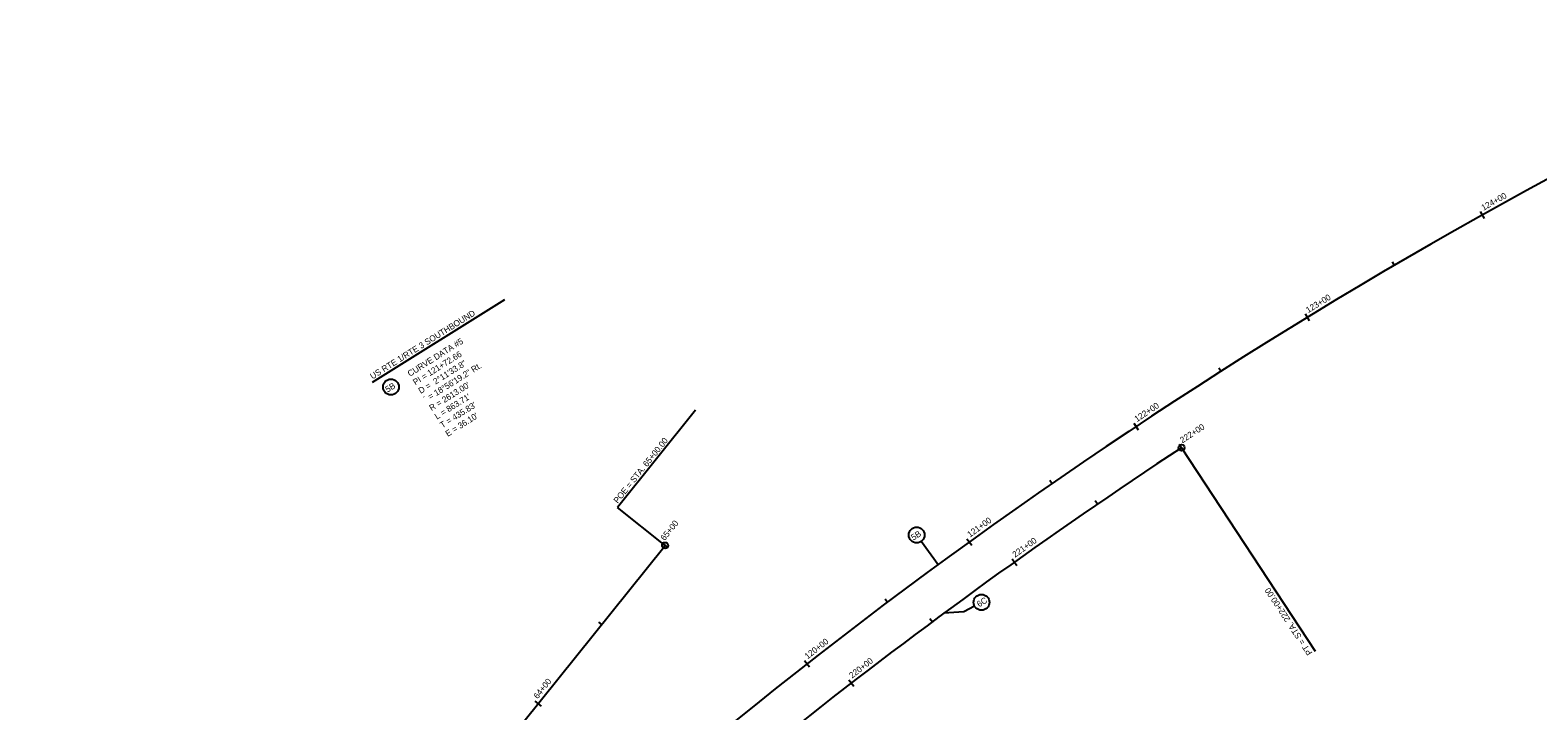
# Model space of a CAD drawing. Extents: x 1667099 to 1669772, y 337408 to 340124.
# Drawn here: x 1667828 to 1668571, y 339310 to 339645 of the extents above; entities that cross this region are included whole.
import ezdxf

# ---------------------------------------------------------------- set-up
doc = ezdxf.new("R2010")
doc.units = 0
for name, color, linetype in [('Alignment', 7, 'Continuous'), ('ANNOTATION', 7, 'Continuous'), ('D_Roadway_Centerline', 7, 'Continuous'), ('D_Roadway_Centerline_CurveData', 7, 'Continuous'), ('D_Roadway_Centerline_Flags', 7, 'Continuous'), ('D_Roadway_Centerline_Text', 7, 'Continuous'), ('Default', 7, 'Continuous'), ('S_Roadway_Edge_Pavement', 7, 'Continuous')]:
    doc.layers.add(name, color=color, linetype=linetype)

msp = doc.modelspace()

# ---------------------------------------------------------------- linework, layer by layer
at = {"layer": 'Alignment'}
msp.add_arc((1669829.28, 337256.22), 2612, 123.30352, 133.53618, dxfattribs=at)
at = {"layer": 'ANNOTATION'}
for p, q in [((1667996.45, 339471.53), (1668061.61, 339512.39)), ((1668266.88, 339393.07), (1668275.23, 339381.66)), ((1668293.09, 339361.15), (1668287.75, 339358.27)), ((1668287.75, 339358.27), (1668277.9, 339357.59))]:
    msp.add_line(p, q, dxfattribs=at)
for centre in [(1668005.47, 339469.19), (1668264.57, 339396.21), (1668296.52, 339363)]:
    msp.add_circle(centre, 3.9, dxfattribs=at)
at = {"layer": 'D_Roadway_Centerline'}
msp.add_line((1667827.67, 339001.09), (1668140.6, 339391.06), dxfattribs=at)
for centre, radius, start, end in [((1669819.48, 337273.8), 2613, 114.83733, 133.776), ((1669829.28, 337256.22), 2612, 123.30352, 133.53618)]:
    msp.add_arc(centre, radius, start, end, dxfattribs=at)
at = {"layer": 'D_Roadway_Centerline_Flags'}
msp.add_line((1668155.64, 339457.73), (1668117.2, 339409.84), dxfattribs=at)
for points in [[(1668395.1, 339439.26), (1668460.99, 339338.97)], [(1668140.6, 339391.06), (1668117.2, 339409.84)]]:
    msp.add_lwpolyline(points, dxfattribs=at)
for centre in [(1668395.1, 339439.26), (1668140.6, 339391.06)]:
    msp.add_circle(centre, 1.5, dxfattribs=at)
at = {"layer": 'D_Roadway_Centerline_Text'}
for points in [[(1668542.35, 339555.72), (1668544.3, 339552.23)], [(1668498.92, 339530.87), (1668499.93, 339529.14)], [(1668455.97, 339505.19), (1668458.06, 339501.77)], [(1668413.53, 339478.69), (1668414.6, 339477)], [(1668371.6, 339451.39), (1668373.81, 339448.05)], [(1668394, 339440.93), (1668396.2, 339437.59)], [(1668394, 339440.93), (1668396.2, 339437.59)], [(1668330.2, 339423.28), (1668331.34, 339421.64)], [(1668352.59, 339413.15), (1668353.71, 339411.5)], [(1668139.04, 339392.31), (1668142.16, 339389.81)], [(1668289.34, 339394.39), (1668291.68, 339391.15)], [(1668311.57, 339384.49), (1668313.89, 339381.24)], [(1668249.05, 339364.73), (1668250.25, 339363.13)], [(1668107.75, 339353.31), (1668109.31, 339352.06)], [(1668271.11, 339355.05), (1668272.3, 339353.45)], [(1668209.33, 339334.3), (1668211.79, 339331.14)], [(1668231.22, 339324.84), (1668233.67, 339321.68)], [(1668076.45, 339314.32), (1668079.57, 339311.81)]]:
    msp.add_lwpolyline(points, dxfattribs=at)
at = {"layer": 'Default'}
msp.add_line((1667827.67, 339001.09), (1668140.6, 339391.06), dxfattribs=at)
at = {"layer": 'S_Roadway_Edge_Pavement'}
msp.add_arc((1669819.48, 337273.8), 2613, 114.83733, 133.776, dxfattribs=at)

# ---------------------------------------------------------------- texts
at = {"layer": 'ANNOTATION'}
for s, rotation, p in [('US RTE 1/RTE 3 SOUTHBOUND', 32.08927, (1667996.38, 339472.84)), ('5B', 31.85504, (1668003.86, 339466.4)), ('5B', 31.85504, (1668262.96, 339393.42)), ('6C', 32.55289, (1668295.43, 339360.5))]:
    msp.add_text(s, height=3, rotation=rotation, dxfattribs=at).set_placement(p)
at = {"layer": 'D_Roadway_Centerline_CurveData'}
for s, p in [('CURVE DATA #5', (1668014.85, 339474.18)), ('PI = 121+72.66', (1668017.51, 339469.95)), ('D =  2%%d11\'33.8"', (1668020.18, 339465.72)), ('´ = 18%%d56\'19.2" Rt.', (1668022.84, 339461.49)), ("R = 2613.00'", (1668025.5, 339457.26)), ("L = 863.71'", (1668028.17, 339453.03)), ("T = 435.83'", (1668030.83, 339448.79)), ("E = 36.10'", (1668033.49, 339444.56))]:
    msp.add_text(s, height=3, rotation=32.18617, dxfattribs=at).set_placement(p)
at = {"layer": 'D_Roadway_Centerline_Flags'}
for s, rotation, p in [('POE = STA. 65+00.00', 51.2548, (1668117.26, 339411.54)), ('PT = STA. 222+00.00', 123.30352, (1668459.73, 339338.14))]:
    msp.add_text(s, height=3, rotation=rotation, dxfattribs=at).set_placement(p)
at = {"layer": 'D_Roadway_Centerline_Text'}
for s, rotation, p in [('124+00', 29.23463, (1668543.9, 339556.02)), ('123+00', 31.42735, (1668457.51, 339505.54)), ('122+00', 33.62007, (1668373.12, 339451.8)), ('222+00', 33.30352, (1668395.53, 339441.34)), ('222+00', 33.30352, (1668395.53, 339441.34)), ('121+00', 35.81279, (1668290.85, 339394.87)), ('65+00', 51.2548, (1668140.37, 339393.17)), ('221+00', 35.49337, (1668313.08, 339384.96)), ('120+00', 38.00551, (1668210.82, 339334.83)), ('220+00', 37.68693, (1668232.71, 339325.36)), ('64+00', 51.2548, (1668077.78, 339315.17))]:
    msp.add_text(s, height=3, rotation=rotation, dxfattribs=at).set_placement(p)

doc.saveas('drawing.dxf')
